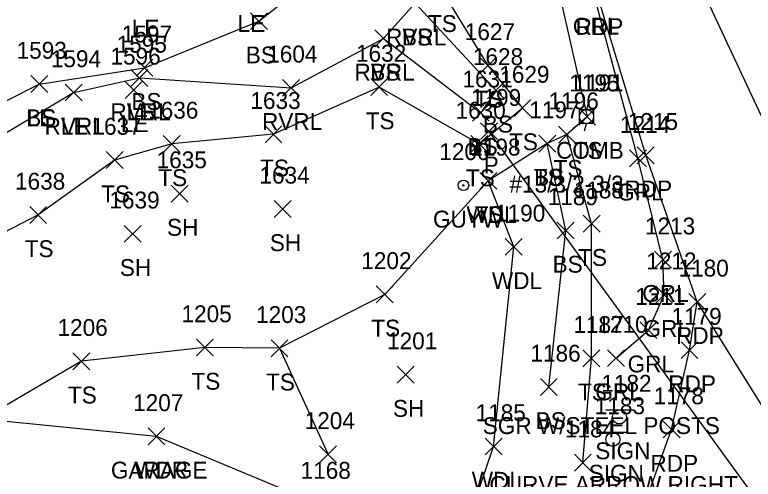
# Model space of a CAD drawing. Extents: x 1620157 to 1620595, y 115111 to 117885.
# Drawn here: x 1620275.8 to 1620363.2, y 115303.5 to 115358.6 of the extents above; entities that cross this region are included whole.
import ezdxf

# ---------------------------------------------------------------- set-up
doc = ezdxf.new("R2010")
doc.units = 0
for name, color, linetype in [('D_A', 7, 'Continuous'), ('D_I', 7, 'Continuous'), ('D_TIC', 7, 'Continuous'), ('DCP', 7, 'Continuous'), ('L_A', 7, 'Continuous'), ('L_I', 7, 'Continuous'), ('L_TIC', 7, 'Continuous'), ('LAWA', 7, 'Continuous'), ('LAWE', 7, 'Continuous'), ('LBC', 7, 'Continuous'), ('LELB', 7, 'Continuous'), ('P_A', 7, 'Continuous'), ('P_I', 7, 'Continuous'), ('P_TIC', 7, 'Continuous'), ('PET', 7, 'Continuous'), ('PRC', 7, 'Continuous'), ('R_A', 7, 'Continuous'), ('R_C', 7, 'Continuous'), ('R_I', 7, 'Continuous'), ('R_TIC', 7, 'Continuous'), ('RGR', 7, 'Continuous'), ('S_A', 7, 'Continuous'), ('S_C', 7, 'Continuous'), ('S_I', 7, 'Continuous'), ('SSGN', 7, 'Continuous'), ('U_A', 7, 'Continuous'), ('U_C', 7, 'Continuous'), ('U_I', 7, 'Continuous'), ('UP', 7, 'Continuous'), ('UPGW', 7, 'Continuous')]:
    doc.layers.add(name, color=color, linetype=linetype)

msp = doc.modelspace()

# ---------------------------------------------------------------- linework, layer by layer
at = {"layer": 'D_TIC'}
for points in [[(1620330.919, 115343.781), (1620332.919, 115345.781)], [(1620332.919, 115343.781), (1620330.919, 115345.781)]]:
    msp.add_lwpolyline(points, dxfattribs=at)
at = {"layer": 'DCP'}
msp.add_lwpolyline([(1620401.963, 115248.346), (1620331.919, 115344.781)], dxfattribs=at)
at = {"layer": 'L_TIC'}
for points in [[(1620303.673, 115356.818), (1620305.673, 115358.818)], [(1620305.673, 115356.818), (1620303.673, 115358.818)], [(1620318.423, 115354.785), (1620320.423, 115356.785)], [(1620320.423, 115354.785), (1620318.423, 115356.785)], [(1620318.423, 115354.785), (1620320.423, 115356.785)], [(1620320.423, 115354.785), (1620318.423, 115356.785)], [(1620330.798, 115351.573), (1620332.798, 115353.573)], [(1620332.798, 115351.573), (1620330.798, 115353.573)], [(1620290.124, 115351.303), (1620292.124, 115353.303)], [(1620292.124, 115351.303), (1620290.124, 115353.303)], [(1620289.514, 115350.088), (1620291.514, 115352.088)], [(1620291.514, 115350.088), (1620289.514, 115352.088)], [(1620289.514, 115350.088), (1620291.514, 115352.088)], [(1620291.514, 115350.088), (1620289.514, 115352.088)], [(1620277.661, 115349.372), (1620279.661, 115351.372)], [(1620279.661, 115349.372), (1620277.661, 115351.372)], [(1620277.661, 115349.372), (1620279.661, 115351.372)], [(1620279.661, 115349.372), (1620277.661, 115351.372)], [(1620317.913, 115349.016), (1620319.913, 115351.016)], [(1620319.913, 115349.016), (1620317.913, 115351.016)], [(1620281.718, 115348.37), (1620283.718, 115350.37)], [(1620283.718, 115348.37), (1620281.718, 115350.37)], [(1620281.718, 115348.37), (1620283.718, 115350.37)], [(1620283.718, 115348.37), (1620281.718, 115350.37)], [(1620288.839, 115348.676), (1620290.839, 115350.676)], [(1620290.839, 115348.676), (1620288.839, 115350.676)], [(1620307.474, 115348.924), (1620309.474, 115350.924)], [(1620309.474, 115348.924), (1620307.474, 115350.924)], [(1620331.761, 115348.618), (1620333.761, 115350.618)], [(1620333.761, 115348.618), (1620331.761, 115350.618)], [(1620334.893, 115346.526), (1620336.893, 115348.526)], [(1620336.893, 115346.526), (1620334.893, 115348.526)], [(1620329.957, 115345.97), (1620331.957, 115347.97)], [(1620331.957, 115345.97), (1620329.957, 115347.97)], [(1620329.957, 115345.97), (1620331.957, 115347.97)], [(1620331.957, 115345.97), (1620329.957, 115347.97)], [(1620342.561, 115345.497), (1620344.561, 115347.497)], [(1620344.561, 115345.497), (1620342.561, 115347.497)], [(1620305.405, 115343.415), (1620307.405, 115345.415)], [(1620307.405, 115343.415), (1620305.405, 115345.415)], [(1620340.166, 115343.372), (1620342.166, 115345.372)], [(1620342.166, 115343.372), (1620340.166, 115345.372)], [(1620340.166, 115343.372), (1620342.166, 115345.372)], [(1620342.166, 115343.372), (1620340.166, 115345.372)], [(1620293.346, 115342.273), (1620295.346, 115344.273)], [(1620295.346, 115342.273), (1620293.346, 115344.273)], [(1620329.791, 115342.259), (1620331.791, 115344.259)], [(1620331.791, 115342.259), (1620329.791, 115344.259)], [(1620337.827, 115342.311), (1620339.827, 115344.311)], [(1620339.827, 115342.311), (1620337.827, 115344.311)], [(1620337.827, 115342.311), (1620339.827, 115344.311)], [(1620339.827, 115342.311), (1620337.827, 115344.311)], [(1620286.578, 115340.357), (1620288.578, 115342.357)], [(1620288.578, 115340.357), (1620286.578, 115342.357)], [(1620330.839, 115337.897), (1620332.839, 115339.897)], [(1620332.839, 115337.897), (1620330.839, 115339.897)], [(1620330.839, 115337.897), (1620332.839, 115339.897)], [(1620332.839, 115337.897), (1620330.839, 115339.897)], [(1620294.296, 115336.389), (1620296.296, 115338.389)], [(1620296.296, 115336.389), (1620294.296, 115338.389)], [(1620306.476, 115334.57), (1620308.476, 115336.57)], [(1620308.476, 115334.57), (1620306.476, 115336.57)], [(1620277.524, 115333.856), (1620279.524, 115335.856)], [(1620279.524, 115333.856), (1620277.524, 115335.856)], [(1620343.086, 115332.817), (1620345.086, 115334.817)], [(1620345.086, 115332.817), (1620343.086, 115334.817)], [(1620288.709, 115331.623), (1620290.709, 115333.623)], [(1620290.709, 115331.623), (1620288.709, 115333.623)], [(1620340.015, 115332.016), (1620342.015, 115334.016)], [(1620342.015, 115332.016), (1620340.015, 115334.016)], [(1620333.855, 115330.074), (1620335.855, 115332.074)], [(1620335.855, 115330.074), (1620333.855, 115332.074)], [(1620318.572, 115324.443), (1620320.572, 115326.443)], [(1620320.572, 115324.443), (1620318.572, 115326.443)], [(1620297.273, 115318.141), (1620299.273, 115320.141)], [(1620299.273, 115318.141), (1620297.273, 115320.141)], [(1620306.11, 115318.051), (1620308.11, 115320.051)], [(1620308.11, 115318.051), (1620306.11, 115320.051)], [(1620306.11, 115318.051), (1620308.11, 115320.051)], [(1620308.11, 115318.051), (1620306.11, 115320.051)], [(1620343.059, 115316.867), (1620345.059, 115318.867)], [(1620345.059, 115316.867), (1620343.059, 115318.867)], [(1620282.642, 115316.517), (1620284.642, 115318.517)], [(1620284.642, 115316.517), (1620282.642, 115318.517)], [(1620321.06, 115314.931), (1620323.06, 115316.931)], [(1620323.06, 115314.931), (1620321.06, 115316.931)], [(1620338.011, 115313.475), (1620340.011, 115315.475)], [(1620340.011, 115313.475), (1620338.011, 115315.475)], [(1620291.544, 115307.613), (1620293.544, 115309.613)], [(1620293.544, 115307.613), (1620291.544, 115309.613)], [(1620291.544, 115307.613), (1620293.544, 115309.613)], [(1620293.544, 115307.613), (1620291.544, 115309.613)], [(1620331.468, 115306.412), (1620333.468, 115308.412)], [(1620333.468, 115306.412), (1620331.468, 115308.412)], [(1620311.865, 115305.479), (1620313.865, 115307.479)], [(1620313.865, 115305.479), (1620311.865, 115307.479)], [(1620342.048, 115304.499), (1620344.048, 115306.499)], [(1620344.048, 115304.499), (1620342.048, 115306.499)]]:
    msp.add_lwpolyline(points, dxfattribs=at)
at = {"layer": 'LAWA'}
for points in [[(1620311.784, 115300.587), (1620328.285, 115295.066), (1620332.468, 115307.412), (1620334.855, 115331.074), (1620331.839, 115338.897)], [(1620292.544, 115308.613), (1620271.873, 115310.647)]]:
    msp.add_lwpolyline(points, dxfattribs=at)
at = {"layer": 'LAWE'}
msp.add_lwpolyline([(1620231.187, 115341.28), (1620255.832, 115340.835), (1620271.825, 115342.909), (1620282.718, 115349.37), (1620290.514, 115351.088), (1620308.474, 115349.924), (1620319.423, 115355.785), (1620323.167, 115359.94), (1620321.602, 115374.201), (1620322.123, 115377.536), (1620326.931, 115387.408)], dxfattribs=at)
at = {"layer": 'LBC'}
msp.add_lwpolyline([(1620297.895, 115266.887), (1620311.784, 115300.587), (1620292.544, 115308.613)], dxfattribs=at)
at = {"layer": 'LELB'}
for points in [[(1620335.319, 115385.442), (1620337.864, 115371.7), (1620343.561, 115346.497), (1620341.166, 115344.372)], [(1620230.717, 115342.258), (1620255.446, 115343.763), (1620266.003, 115344.013), (1620278.661, 115350.372), (1620291.124, 115352.303), (1620304.673, 115357.818), (1620320.504, 115370.294)], [(1620332.004, 115369.254), (1620327.77, 115368.93), (1620326.291, 115361.539), (1620331.798, 115352.573), (1620335.893, 115347.526), (1620330.791, 115343.259), (1620318.913, 115350.016), (1620306.405, 115344.415), (1620294.346, 115343.273), (1620287.578, 115341.357), (1620278.524, 115334.856), (1620255.739, 115323.043)], [(1620323.167, 115359.94), (1620332.761, 115349.618), (1620330.957, 115346.97)], [(1620319.423, 115355.785), (1620330.957, 115346.97)], [(1620343.048, 115305.499), (1620344.059, 115317.867), (1620344.086, 115333.817), (1620341.166, 115344.372), (1620338.827, 115343.311), (1620331.839, 115338.897), (1620319.572, 115325.443), (1620307.11, 115319.051), (1620298.273, 115319.141), (1620283.642, 115317.517), (1620271.873, 115310.647)], [(1620339.011, 115314.475), (1620341.015, 115333.016), (1620338.827, 115343.311)], [(1620307.11, 115319.051), (1620312.865, 115306.479)]]:
    msp.add_lwpolyline(points, dxfattribs=at)
at = {"layer": 'P_TIC'}
for points in [[(1620349.492, 115340.932), (1620351.492, 115342.932)], [(1620351.492, 115340.932), (1620349.492, 115342.932)], [(1620355.593, 115323.555), (1620357.593, 115325.555)], [(1620357.593, 115323.555), (1620355.593, 115325.555)], [(1620355.593, 115323.555), (1620357.593, 115325.555)], [(1620357.593, 115323.555), (1620355.593, 115325.555)], [(1620354.676, 115317.837), (1620356.676, 115319.837)], [(1620356.676, 115317.837), (1620354.676, 115319.837)], [(1620352.56, 115308.423), (1620354.56, 115310.423)], [(1620354.56, 115308.423), (1620352.56, 115310.423)]]:
    msp.add_lwpolyline(points, dxfattribs=at)
at = {"layer": 'PET'}
for points in [[(1620562.045, 115139.537), (1620535.961, 115156.898), (1620508.491, 115175.945), (1620479.205, 115196.111), (1620451.098, 115216.616), (1620428.041, 115234.702), (1620407.201, 115256.439), (1620380.209, 115287.874), (1620366.182, 115309.187), (1620356.593, 115324.555), (1620350.492, 115341.932), (1620344.694, 115361.164), (1620336.512, 115388.614), (1620345.687, 115391.553), (1620355.301, 115394.861)], [(1620325.409, 115264.335), (1620337.417, 115277.734), (1620345.225, 115288.919), (1620349.026, 115296.888), (1620353.56, 115309.423), (1620355.676, 115318.837), (1620356.593, 115324.555)]]:
    msp.add_lwpolyline(points, dxfattribs=at)
at = {"layer": 'PRC'}
msp.add_lwpolyline([(1620569.192, 115149.917), (1620542.761, 115168.022), (1620512.114, 115189.578), (1620491.048, 115205.01), (1620469.112, 115221.777), (1620461.731, 115227.824), (1620438.824, 115247.131), (1620418.591, 115266.65), (1620405.031, 115281.948), (1620392.881, 115297.861), (1620380.474, 115316.237), (1620370.644, 115332.813), (1620355.485, 115365.231), (1620348.096, 115384.578), (1620345.687, 115391.553)], dxfattribs=at)
at = {"layer": 'R_TIC'}
for points in [[(1620348.57, 115340.57), (1620350.57, 115342.57)], [(1620350.57, 115340.57), (1620348.57, 115342.57)], [(1620351.529, 115328.549), (1620353.529, 115330.549)], [(1620353.529, 115328.549), (1620351.529, 115330.549)], [(1620351.683, 115324.401), (1620353.683, 115326.401)], [(1620353.683, 115324.401), (1620351.683, 115326.401)], [(1620349.804, 115320.196), (1620351.804, 115322.196)], [(1620351.804, 115320.196), (1620349.804, 115322.196)], [(1620345.982, 115316.888), (1620347.982, 115318.888)], [(1620347.982, 115316.888), (1620345.982, 115318.888)]]:
    msp.add_lwpolyline(points, dxfattribs=at)
at = {"layer": 'RGR'}
msp.add_lwpolyline([(1620346.982, 115317.888), (1620350.804, 115321.196), (1620352.683, 115325.401), (1620352.529, 115329.549), (1620349.57, 115341.57), (1620344.313, 115361.225), (1620336.401, 115388.033)], dxfattribs=at)
at = {"layer": 'SSGN'}
for p, q in [((1620345.733, 115311.756), (1620349.066, 115311.756)), ((1620347.379, 115310.923), (1620347.379, 115310.923)), ((1620344.955, 115309.093), (1620348.288, 115309.093)), ((1620346.602, 115308.26), (1620346.602, 115308.26))]:
    msp.add_line(p, q, dxfattribs=at)
for centre in [(1620347.379, 115310.923), (1620346.602, 115308.26)]:
    msp.add_circle(centre, 0.833, dxfattribs=at)
at = {"layer": 'UP'}
for p, q in [((1620343.73, 115348.178), (1620343.48, 115347.345)), ((1620342.647, 115345.678), (1620342.647, 115347.345)), ((1620342.647, 115347.345), (1620344.314, 115347.345)), ((1620344.314, 115347.345), (1620344.314, 115345.678)), ((1620343.48, 115346.511), (1620343.48, 115346.511)), ((1620344.314, 115345.678), (1620342.647, 115345.678)), ((1620343.23, 115344.845), (1620343.48, 115345.678))]:
    msp.add_line(p, q, dxfattribs=at)
msp.add_circle((1620343.48, 115346.511), 0.833, dxfattribs=at)
at = {"layer": 'UPGW'}
for radius in [0.625, 0.0833]:
    msp.add_circle((1620328.899, 115338.362), radius, dxfattribs=at)

# ---------------------------------------------------------------- texts
at = {"layer": 'D_A'}
msp.add_text('P', height=2, dxfattribs=at).set_placement((1620331.297, 115339.781))
at = {"layer": 'D_I'}
msp.add_text('1199', height=2, dxfattribs=at).set_placement((1620329.785, 115347.781))
at = {"layer": 'L_A'}
for s, p in [('LE', (1620289.609, 115355.996)), ('LE', (1620302.139, 115356.543)), ('TS', (1620324.7, 115356.539)), ('RVRL', (1620319.734, 115354.94)), ('BS', (1620321.608, 115354.94)), ('BS', (1620303.114, 115352.818)), ('RVRL', (1620315.99, 115350.785)), ('BS', (1620317.864, 115350.785)), ('BS', (1620289.565, 115347.303)), ('TS', (1620330.207, 115347.573)), ('RVRL', (1620287.081, 115346.088)), ('LE', (1620289.002, 115346.088)), ('BS', (1620277.102, 115345.372)), ('LE', (1620277.15, 115345.372)), ('LE', (1620288.327, 115344.676)), ('RVRL', (1620305.041, 115344.924)), ('TS', (1620317.322, 115345.016)), ('BS', (1620331.202, 115344.618)), ('RVRL', (1620279.285, 115344.37)), ('LE', (1620281.206, 115344.37)), ('BS', (1620329.398, 115341.97)), ('BS', (1620329.398, 115341.97)), ('TS', (1620334.302, 115342.526)), ('TS', (1620341.971, 115341.497)), ('TS', (1620304.815, 115339.415)), ('TS', (1620339.576, 115339.372)), ('TS', (1620339.576, 115339.372)), ('TS', (1620292.755, 115338.273)), ('TS', (1620329.2, 115338.259)), ('TS', (1620337.237, 115338.311)), ('BS', (1620337.268, 115338.311)), ('TS', (1620285.988, 115336.357)), ('WDL', (1620329.256, 115333.897)), ('TS', (1620330.248, 115333.897)), ('SH', (1620293.784, 115332.389)), ('SH', (1620305.964, 115330.57)), ('TS', (1620276.933, 115329.856)), ('TS', (1620342.495, 115328.817)), ('BS', (1620339.456, 115328.016)), ('SH', (1620288.198, 115327.623)), ('WDL', (1620332.273, 115326.074)), ('TS', (1620317.981, 115320.443)), ('TS', (1620296.683, 115314.141)), ('TS', (1620305.52, 115314.051)), ('TS', (1620305.52, 115314.051)), ('TS', (1620282.051, 115312.517)), ('TS', (1620342.469, 115312.867)), ('SH', (1620320.548, 115310.931)), ('BS', (1620337.452, 115309.475)), ('GARAGE', (1620287.142, 115303.613)), ('WDR', (1620289.906, 115303.613)), ('WDL', (1620329.885, 115302.412))]:
    msp.add_text(s, height=2, dxfattribs=at).set_placement(p)
at = {"layer": 'L_I'}
for s, p in [('1597', (1620288.431, 115355.303)), ('1627', (1620329.058, 115355.573)), ('1593', (1620275.969, 115353.372)), ('1593', (1620275.969, 115353.372)), ('1595', (1620287.821, 115354.088)), ('1595', (1620287.821, 115354.088)), ('1596', (1620287.091, 115352.676)), ('1604', (1620305.655, 115352.924)), ('1632', (1620316.173, 115353.016)), ('1628', (1620330.021, 115352.618)), ('1594', (1620280.025, 115352.37)), ('1594', (1620280.025, 115352.37)), ('1631', (1620328.784, 115349.97)), ('1631', (1620328.784, 115349.97)), ('1629', (1620333.145, 115350.526)), ('1195', (1620341.436, 115349.497)), ('1633', (1620303.665, 115347.415)), ('1196', (1620338.985, 115347.372)), ('1196', (1620338.985, 115347.372)), ('1197', (1620336.701, 115346.311)), ('1197', (1620336.701, 115346.311)), ('1636', (1620291.551, 115346.273)), ('1630', (1620327.964, 115346.259)), ('1637', (1620284.838, 115344.357)), ('1198', (1620329.713, 115341.897)), ('1198', (1620329.713, 115341.897)), ('1635', (1620292.556, 115340.389)), ('1634', (1620304.736, 115338.57)), ('1638', (1620275.784, 115337.856)), ('1188', (1620341.96, 115336.817)), ('1189', (1620338.882, 115336.016)), ('1639', (1620286.962, 115335.623)), ('1190', (1620332.643, 115334.074)), ('1202', (1620316.8, 115328.443)), ('1205', (1620295.502, 115322.141)), ('1203', (1620304.339, 115322.051)), ('1203', (1620304.339, 115322.051)), ('1206', (1620280.815, 115320.517)), ('1187', (1620341.934, 115320.867)), ('1201', (1620319.855, 115318.931)), ('1186', (1620336.83, 115317.475)), ('1207', (1620289.772, 115311.613)), ('1207', (1620289.772, 115311.613)), ('1185', (1620330.342, 115310.412)), ('1204', (1620310.093, 115309.479)), ('1184', (1620340.922, 115308.499)), ('1168', (1620309.611, 115303.587)), ('1168', (1620309.611, 115303.587)), ('1168', (1620309.611, 115303.587))]:
    msp.add_text(s, height=2, dxfattribs=at).set_placement(p)
at = {"layer": 'P_A'}
for p in [(1620342.182, 115356.164), (1620347.98, 115336.932), (1620354.081, 115319.555), (1620354.081, 115319.555), (1620353.164, 115313.837), (1620351.048, 115304.423)]:
    msp.add_text('RDP', height=2, dxfattribs=at).set_placement(p)
at = {"layer": 'P_I'}
for s, p in [('1215', (1620348.366, 115344.932)), ('1180', (1620354.381, 115327.555)), ('1180', (1620354.381, 115327.555)), ('1179', (1620353.542, 115321.837)), ('1178', (1620351.434, 115312.423))]:
    msp.add_text(s, height=2, dxfattribs=at).set_placement(p)
at = {"layer": 'R_A'}
for p in [(1620341.856, 115356.225), (1620347.113, 115336.57), (1620350.072, 115324.549), (1620350.226, 115320.401), (1620348.347, 115316.196), (1620344.526, 115312.888)]:
    msp.add_text('GRL', height=2, dxfattribs=at).set_placement(p)
at = {"layer": 'R_C'}
msp.add_text('SGR W/STEEL POSTS', height=2, dxfattribs=at).set_placement((1620331.187, 115308.888))
at = {"layer": 'R_I'}
for s, p in [('1214', (1620347.444, 115344.57)), ('1213', (1620350.403, 115332.549)), ('1212', (1620350.557, 115328.401)), ('1211', (1620349.245, 115324.196)), ('1210', (1620344.77, 115320.888))]:
    msp.add_text(s, height=2, dxfattribs=at).set_placement(p)
at = {"layer": 'S_A'}
for p in [(1620344.518, 115305.903), (1620343.74, 115303.24)]:
    msp.add_text('SIGN', height=2, dxfattribs=at).set_placement(p)
at = {"layer": 'S_C'}
msp.add_text('CURVE ARROW RIGHT', height=2, dxfattribs=at).set_placement((1620331.982, 115301.903))
at = {"layer": 'S_I'}
for s, p in [('1182', (1620345.234, 115313.903)), ('1183', (1620344.456, 115311.24))]:
    msp.add_text(s, height=2, dxfattribs=at).set_placement(p)
at = {"layer": 'U_A'}
for s, p in [('COMB', (1620339.866, 115341.511)), ('GUYW', (1620325.293, 115333.362))]:
    msp.add_text(s, height=2, dxfattribs=at).set_placement(p)
at = {"layer": 'U_C'}
msp.add_text('#13/3/2-3/3', height=2, dxfattribs=at).set_placement((1620334.347, 115337.511))
at = {"layer": 'U_I'}
for s, p in [('1191', (1620341.922, 115349.511)), ('1200', (1620326.041, 115341.362))]:
    msp.add_text(s, height=2, dxfattribs=at).set_placement(p)

doc.saveas('drawing.dxf')
